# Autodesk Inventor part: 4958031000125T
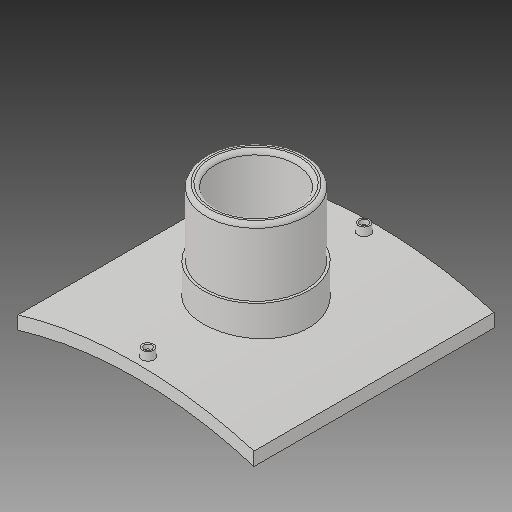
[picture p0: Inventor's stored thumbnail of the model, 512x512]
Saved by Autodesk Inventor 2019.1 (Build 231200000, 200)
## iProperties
Created: 2017-10
Part Number: 4958031000125T
Material: Generic
Description: PLASSON BRANCH SADDLE  1000x125
Document SubType Name: Modeling
Designer: KIM
Mass: 2754.05 g
Surface Area: 3037.44 cm^2
Volume: 2754.05 cm^3
Density: 1 g/cm^3
Appearance: Default
Author: KIM
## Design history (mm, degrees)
derived "495803.ipt"
feature "Solid1::495803.ipt"
tag "TaggingFeature1"
body "Solid1"
other parameters: "d1" = 16, "d2" = 295, "d4" = 0, "d12" = 525.6, "d13" = 14, "d14" = 135, "d16" = 5 deg, "d18" = 4, "d19" = 14, "d20" = 0, "d21" = 3, "d22" = 0, "d23" = 636, "d24" = 131.25, "d25" = 16, "d28" = 0, "d29" = 9.6, "d31" = 0, "d33" = 0, "d36" = 125, "d37" = 84, "d38" = 0, "d39" = 5, "d_1" = 125, "B_" = 295, "x_" = 16, "D_" = 16
